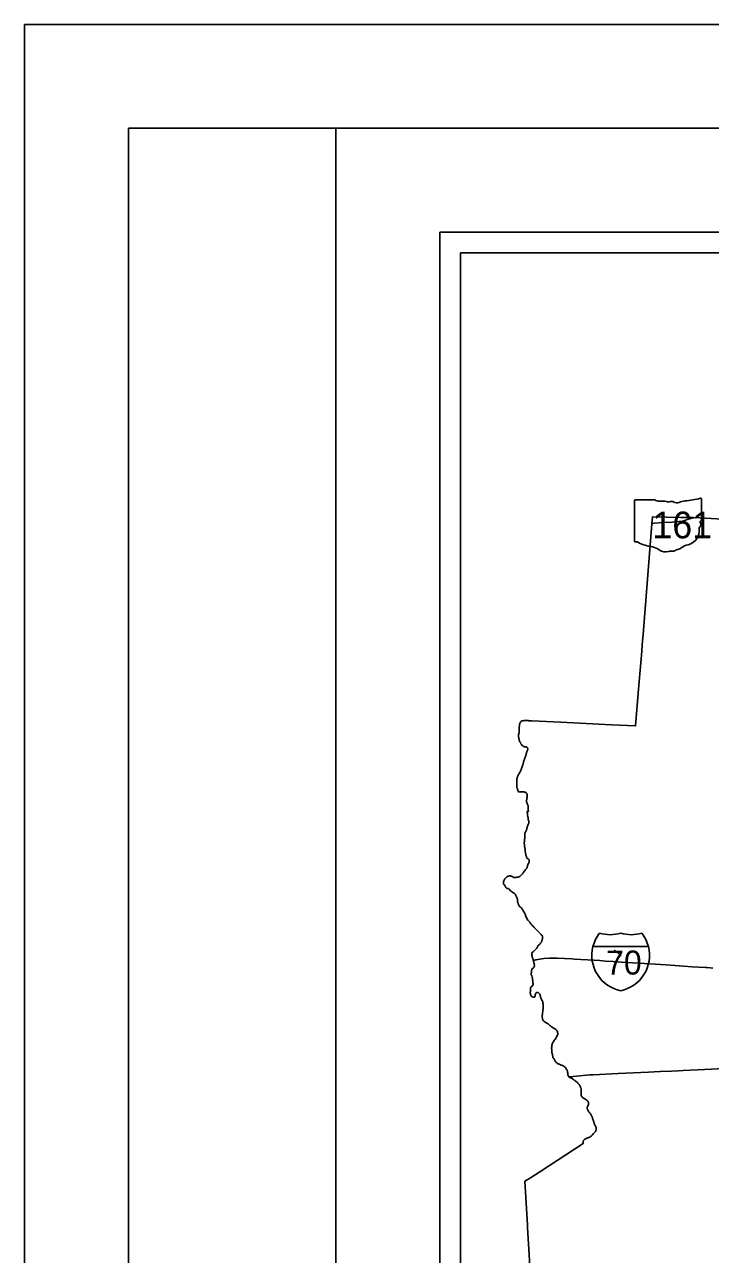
# Model space of a CAD drawing. Extents: x 0 to 34, y 0 to 22.
# Drawn here: x 0 to 3.3, y 16.07 to 22 of the extents above; entities that cross this region are included whole.
import ezdxf

# ---------------------------------------------------------------- set-up
doc = ezdxf.new("R2010")
doc.units = 0
for name, color, linetype in [('GM_X_County', 7, 'Continuous'), ('GM_X_County_Road', 7, 'Continuous'), ('GM_X_Interstate_Route', 7, 'Continuous'), ('GM_X_Interstate_Shield', 7, 'Continuous'), ('GM_X_State_Route', 7, 'Continuous'), ('GM_X_State_Shield', 7, 'Continuous'), ('GM_X_US_Route', 7, 'Continuous'), ('SH_Border', 7, 'Continuous'), ('SH_Cut_Line', 7, 'Continuous'), ('SH_Data', 7, 'Continuous')]:
    doc.layers.add(name, color=color, linetype=linetype)

msp = doc.modelspace()

# ---------------------------------------------------------------- linework, layer by layer
at = {"layer": 'GM_X_County'}
msp.add_lwpolyline([(2.4341, 16.0159), (2.4234, 16.2017), (2.4226, 16.2148), (2.4105, 16.4243), (2.4377, 16.4414), (2.4817, 16.4701), (2.6905, 16.6061), (2.6912, 16.6093), (2.6907, 16.6121), (2.6906, 16.6145), (2.691, 16.6169), (2.6917, 16.6199), (2.6941, 16.6229), (2.6973, 16.6251), (2.7005, 16.6273), (2.7036, 16.6292), (2.7061, 16.6306), (2.7092, 16.6321), (2.7116, 16.6334), (2.7142, 16.6343), (2.7174, 16.6353), (2.7197, 16.6361), (2.7232, 16.6376), (2.7265, 16.6396), (2.7297, 16.6424), (2.7328, 16.6455), (2.7361, 16.6487), (2.739, 16.6522), (2.7416, 16.6551), (2.7446, 16.6579), (2.7476, 16.6612), (2.7503, 16.6646), (2.7522, 16.6675), (2.7531, 16.6699), (2.7538, 16.6725), (2.7541, 16.6756), (2.7543, 16.678), (2.754, 16.6804), (2.7532, 16.683), (2.7516, 16.6861), (2.7504, 16.6899), (2.7489, 16.6932), (2.7481, 16.6955), (2.7466, 16.6986), (2.7452, 16.7016), (2.7439, 16.7042), (2.7429, 16.7076), (2.7423, 16.7104), (2.7413, 16.7136), (2.7403, 16.7161), (2.7393, 16.719), (2.7381, 16.7219), (2.7373, 16.7242), (2.7364, 16.7274), (2.7362, 16.7297), (2.7354, 16.7328), (2.7341, 16.7352), (2.7325, 16.7384), (2.7305, 16.7421), (2.7292, 16.7446), (2.7278, 16.7474), (2.7254, 16.7508), (2.7236, 16.7534), (2.7218, 16.7557), (2.7189, 16.7595), (2.7172, 16.762), (2.7156, 16.7644), (2.7141, 16.7667), (2.7126, 16.77), (2.7114, 16.7732), (2.7108, 16.7757), (2.7105, 16.7781), (2.7107, 16.781), (2.7119, 16.7845), (2.7136, 16.7869), (2.7158, 16.7906), (2.7167, 16.793), (2.7171, 16.7953), (2.7173, 16.7989), (2.717, 16.8017), (2.7164, 16.8044), (2.7158, 16.8068), (2.7145, 16.8098), (2.7117, 16.8128), (2.7088, 16.8149), (2.7039, 16.8183), (2.7016, 16.8195), (2.6987, 16.8211), (2.6956, 16.823), (2.6924, 16.8251), (2.6899, 16.8271), (2.6876, 16.829), (2.6848, 16.8318), (2.6826, 16.8349), (2.6819, 16.8377), (2.6816, 16.8406), (2.6816, 16.8437), (2.6817, 16.8467), (2.6819, 16.8505), (2.682, 16.8539), (2.6821, 16.8571), (2.682, 16.8603), (2.6817, 16.8627), (2.6814, 16.8662), (2.6811, 16.8691), (2.68, 16.874), (2.6791, 16.8769), (2.6782, 16.8794), (2.6766, 16.8826), (2.6755, 16.885), (2.6737, 16.888), (2.6713, 16.8907), (2.6689, 16.8935), (2.6657, 16.8966), (2.6634, 16.8998), (2.6609, 16.9026), (2.6579, 16.9053), (2.6549, 16.9075), (2.6518, 16.9095), (2.6485, 16.912), (2.6427, 16.9162), (2.6403, 16.9175), (2.6375, 16.9193), (2.6343, 16.9209), (2.6318, 16.9222), (2.6287, 16.9234), (2.6263, 16.9244), (2.6231, 16.9268), (2.622, 16.9284), (2.6205, 16.9308), (2.6189, 16.934), (2.6179, 16.9372), (2.6171, 16.9408), (2.6169, 16.9432), (2.6168, 16.9462), (2.6166, 16.9499), (2.6161, 16.9524), (2.6151, 16.9557), (2.6142, 16.9584), (2.613, 16.9607), (2.6113, 16.9637), (2.6096, 16.9668), (2.6084, 16.9691), (2.606, 16.9722), (2.6036, 16.9741), (2.6012, 16.9761), (2.5979, 16.9786), (2.5947, 16.9803), (2.5923, 16.9816), (2.59, 16.9827), (2.5877, 16.9835), (2.5853, 16.9847), (2.5822, 16.9857), (2.5799, 16.9866), (2.5775, 16.9878), (2.575, 16.9887), (2.5725, 16.9897), (2.5702, 16.9908), (2.5672, 16.992), (2.564, 16.9945), (2.5613, 16.9972), (2.5591, 17.0003), (2.5564, 17.0036), (2.5541, 17.0068), (2.5524, 17.0103), (2.551, 17.0127), (2.5497, 17.0154), (2.5474, 17.019), (2.5459, 17.0221), (2.5447, 17.0266), (2.544, 17.0298), (2.5435, 17.0331), (2.5429, 17.0365), (2.5419, 17.0397), (2.541, 17.0429), (2.5404, 17.0457), (2.5402, 17.0481), (2.54, 17.0531), (2.5399, 17.0557), (2.5399, 17.0582), (2.5396, 17.0613), (2.5394, 17.0641), (2.5395, 17.0673), (2.5396, 17.0704), (2.5398, 17.0738), (2.54, 17.0772), (2.5405, 17.0798), (2.5415, 17.0832), (2.5425, 17.0864), (2.5441, 17.0896), (2.5459, 17.0929), (2.5475, 17.0954), (2.5488, 17.0978), (2.5504, 17.1004), (2.5523, 17.1038), (2.5551, 17.1074), (2.5575, 17.1101), (2.5591, 17.1139), (2.5609, 17.117), (2.5627, 17.1202), (2.5645, 17.1227), (2.5663, 17.1262), (2.5676, 17.129), (2.5686, 17.1322), (2.5688, 17.1351), (2.5687, 17.138), (2.5681, 17.1413), (2.5669, 17.1445), (2.566, 17.1475), (2.565, 17.1501), (2.5631, 17.1529), (2.5612, 17.1551), (2.558, 17.1574), (2.5553, 17.1588), (2.5521, 17.1608), (2.5498, 17.1622), (2.5465, 17.1644), (2.5442, 17.166), (2.5415, 17.1677), (2.539, 17.1694), (2.5367, 17.1705), (2.5333, 17.1734), (2.5309, 17.1758), (2.5277, 17.1787), (2.5253, 17.1804), (2.5223, 17.1827), (2.519, 17.1846), (2.5157, 17.1865), (2.5126, 17.1884), (2.5087, 17.1906), (2.5059, 17.1925), (2.5035, 17.194), (2.5002, 17.197), (2.4978, 17.2001), (2.4967, 17.2025), (2.4961, 17.2053), (2.4955, 17.2081), (2.4949, 17.2114), (2.4943, 17.2145), (2.4939, 17.2171), (2.4938, 17.2196), (2.4939, 17.2222), (2.4943, 17.2256), (2.4948, 17.2283), (2.4954, 17.2319), (2.4957, 17.2348), (2.4959, 17.2373), (2.4961, 17.2389), (2.4962, 17.2396), (2.4965, 17.2423), (2.4969, 17.2447), (2.4973, 17.2478), (2.4977, 17.2505), (2.4979, 17.2533), (2.4983, 17.256), (2.4987, 17.2593), (2.4988, 17.2619), (2.499, 17.2643), (2.4991, 17.2667), (2.4993, 17.2691), (2.4992, 17.2718), (2.4989, 17.2748), (2.4986, 17.2775), (2.4977, 17.2836), (2.4971, 17.2867), (2.4965, 17.2895), (2.4949, 17.2927), (2.4935, 17.2952), (2.4923, 17.2977), (2.4912, 17.3), (2.49, 17.3031), (2.4889, 17.306), (2.4875, 17.3092), (2.4864, 17.3119), (2.4856, 17.3151), (2.4851, 17.3174), (2.4843, 17.3204), (2.4837, 17.3227), (2.4821, 17.3261), (2.4808, 17.3284), (2.4778, 17.3317), (2.4749, 17.3338), (2.47, 17.3342), (2.4676, 17.3335), (2.4653, 17.3322), (2.4624, 17.3289), (2.4612, 17.3261), (2.4607, 17.3226), (2.4607, 17.3202), (2.4606, 17.3178), (2.4589, 17.3142), (2.4564, 17.3123), (2.4541, 17.3117), (2.4513, 17.3113), (2.445, 17.3135), (2.4421, 17.3156), (2.4398, 17.3186), (2.4384, 17.3216), (2.4373, 17.3244), (2.437, 17.3271), (2.4365, 17.3303), (2.4365, 17.3328), (2.4367, 17.336), (2.4369, 17.3391), (2.4371, 17.3415), (2.4374, 17.3446), (2.4377, 17.3479), (2.438, 17.3502), (2.4381, 17.353), (2.4377, 17.3562), (2.4396, 17.3595), (2.4428, 17.3624), (2.4459, 17.3644), (2.4493, 17.3699), (2.4498, 17.3724), (2.4498, 17.3749), (2.4497, 17.378), (2.4495, 17.3806), (2.4488, 17.3841), (2.4484, 17.3872), (2.4481, 17.3898), (2.4478, 17.3944), (2.4477, 17.3967), (2.4474, 17.3992), (2.4469, 17.4023), (2.4464, 17.4046), (2.4454, 17.4078), (2.4436, 17.4149), (2.4422, 17.418), (2.4414, 17.421), (2.4412, 17.4241), (2.4413, 17.4271), (2.4416, 17.4303), (2.4419, 17.4333), (2.4422, 17.4357), (2.4425, 17.4386), (2.4428, 17.4417), (2.4437, 17.4447), (2.4464, 17.4492), (2.45, 17.4508), (2.4522, 17.4538), (2.4544, 17.4566), (2.4557, 17.4596), (2.4562, 17.4628), (2.4562, 17.4661), (2.4557, 17.4693), (2.4554, 17.472), (2.4549, 17.4746), (2.4539, 17.4778), (2.4537, 17.4788), (2.453, 17.4812), (2.4525, 17.4839), (2.4517, 17.4865), (2.4511, 17.4883), (2.4498, 17.493), (2.4487, 17.4958), (2.448, 17.4988), (2.447, 17.5019), (2.446, 17.5047), (2.445, 17.5112), (2.4439, 17.5142), (2.4435, 17.5175), (2.4437, 17.5208), (2.4445, 17.5233), (2.4476, 17.528), (2.4504, 17.531), (2.4531, 17.5337), (2.4556, 17.5359), (2.4589, 17.539), (2.4617, 17.5419), (2.4654, 17.5452), (2.4674, 17.548), (2.4697, 17.5515), (2.4714, 17.5546), (2.4726, 17.5577), (2.4748, 17.5612), (2.4781, 17.5645), (2.4805, 17.5664), (2.4834, 17.5693), (2.4857, 17.5717), (2.4885, 17.5748), (2.4898, 17.5772), (2.491, 17.5796), (2.4923, 17.5827), (2.4932, 17.5857), (2.4943, 17.5893), (2.4949, 17.5924), (2.4955, 17.5957), (2.4958, 17.5997), (2.4956, 17.6021), (2.4948, 17.6052), (2.4932, 17.6083), (2.4903, 17.6112), (2.4884, 17.6137), (2.4852, 17.617), (2.4823, 17.6203), (2.4794, 17.6231), (2.4763, 17.6267), (2.4736, 17.6295), (2.4703, 17.6329), (2.4679, 17.6355), (2.4652, 17.638), (2.462, 17.6414), (2.4589, 17.6448), (2.4559, 17.6475), (2.4529, 17.6506), (2.45, 17.6541), (2.4459, 17.6578), (2.4429, 17.6606), (2.4402, 17.6639), (2.4378, 17.667), (2.436, 17.6698), (2.4339, 17.6728), (2.4314, 17.676), (2.429, 17.6787), (2.4254, 17.6834), (2.4204, 17.6906), (2.4177, 17.6962), (2.4142, 17.7033), (2.4132, 17.7065), (2.4129, 17.7093), (2.4123, 17.7116), (2.411, 17.7147), (2.409, 17.7178), (2.4058, 17.7227), (2.4025, 17.7285), (2.3988, 17.7338), (2.3974, 17.7361), (2.3957, 17.7386), (2.3934, 17.7417), (2.3907, 17.7447), (2.3881, 17.7472), (2.3851, 17.749), (2.3825, 17.752), (2.3811, 17.7548), (2.3799, 17.7581), (2.3788, 17.7606), (2.3776, 17.7642), (2.3765, 17.7673), (2.3757, 17.7701), (2.3752, 17.7732), (2.375, 17.7766), (2.3749, 17.779), (2.3747, 17.7819), (2.3743, 17.7846), (2.3737, 17.7877), (2.373, 17.7901), (2.3719, 17.7925), (2.3707, 17.7949), (2.3689, 17.798), (2.3671, 17.8015), (2.3655, 17.8044), (2.3633, 17.8077), (2.3614, 17.81), (2.3587, 17.8128), (2.3557, 17.8145), (2.3525, 17.8167), (2.3502, 17.8177), (2.347, 17.8197), (2.3443, 17.822), (2.3412, 17.8251), (2.3381, 17.8285), (2.3354, 17.8316), (2.333, 17.8338), (2.3306, 17.835), (2.3279, 17.8357), (2.3253, 17.836), (2.3228, 17.8364), (2.3202, 17.8388), (2.3186, 17.8411), (2.3172, 17.8437), (2.315, 17.8473), (2.3133, 17.8501), (2.3115, 17.8525), (2.3095, 17.8555), (2.3082, 17.8587), (2.3075, 17.8621), (2.3075, 17.8646), (2.3076, 17.867), (2.3081, 17.8702), (2.309, 17.8726), (2.3102, 17.8758), (2.3115, 17.8782), (2.3138, 17.8816), (2.3158, 17.8842), (2.3183, 17.8871), (2.3216, 17.8896), (2.324, 17.8915), (2.3266, 17.8932), (2.33, 17.8946), (2.3325, 17.8954), (2.335, 17.8962), (2.3375, 17.8964), (2.3398, 17.8964), (2.3428, 17.8957), (2.3461, 17.8945), (2.3492, 17.893), (2.3533, 17.8907), (2.3565, 17.8893), (2.3601, 17.8884), (2.363, 17.8881), (2.3656, 17.8884), (2.3694, 17.8891), (2.3724, 17.8897), (2.3751, 17.8902), (2.3776, 17.8908), (2.3808, 17.8919), (2.3834, 17.8928), (2.3866, 17.8939), (2.3895, 17.8959), (2.3931, 17.9004), (2.3957, 17.9037), (2.3983, 17.9069), (2.4006, 17.9092), (2.4032, 17.9127), (2.4058, 17.9159), (2.4076, 17.9185), (2.4099, 17.9215), (2.4121, 17.9245), (2.4136, 17.9269), (2.4167, 17.9301), (2.4193, 17.9341), (2.4208, 17.9371), (2.4219, 17.9403), (2.4224, 17.9429), (2.4233, 17.9461), (2.4244, 17.9497), (2.4261, 17.9538), (2.4273, 17.9562), (2.4296, 17.9597), (2.4305, 17.9621), (2.4311, 17.9648), (2.4313, 17.9674), (2.4312, 17.9707), (2.4305, 17.9744), (2.4286, 17.9775), (2.4256, 17.9793), (2.4218, 17.981), (2.4203, 17.9829), (2.4197, 17.9836), (2.4188, 17.9868), (2.4177, 17.99), (2.4164, 17.9934), (2.4158, 17.9958), (2.4152, 17.9981), (2.4144, 18.0014), (2.4138, 18.0047), (2.4132, 18.0077), (2.4128, 18.01), (2.4124, 18.0124), (2.4121, 18.0147), (2.4118, 18.0179), (2.4117, 18.0204), (2.4114, 18.0241), (2.4112, 18.0274), (2.4107, 18.0305), (2.4099, 18.0328), (2.4092, 18.0361), (2.4086, 18.0393), (2.4082, 18.043), (2.408, 18.0453), (2.4079, 18.0487), (2.4077, 18.0514), (2.4076, 18.0544), (2.4075, 18.057), (2.4076, 18.0595), (2.408, 18.0624), (2.4082, 18.0648), (2.4084, 18.0677), (2.4088, 18.0707), (2.4093, 18.0742), (2.4097, 18.0768), (2.41, 18.0793), (2.4103, 18.0828), (2.4103, 18.0861), (2.4103, 18.0891), (2.4105, 18.0919), (2.4105, 18.0942), (2.4107, 18.0965), (2.4108, 18.0991), (2.4109, 18.1016), (2.4119, 18.1052), (2.4139, 18.1081), (2.4157, 18.1112), (2.4169, 18.1142), (2.4182, 18.1174), (2.4188, 18.12), (2.4196, 18.1223), (2.4204, 18.1255), (2.4214, 18.1294), (2.4221, 18.132), (2.4233, 18.1361), (2.4239, 18.1384), (2.4253, 18.1423), (2.4266, 18.1448), (2.428, 18.1477), (2.4295, 18.1512), (2.4299, 18.1536), (2.4298, 18.156), (2.4296, 18.1583), (2.4291, 18.1606), (2.4283, 18.163), (2.4277, 18.1653), (2.427, 18.1682), (2.4266, 18.171), (2.4262, 18.1734), (2.4261, 18.1758), (2.4257, 18.1782), (2.4252, 18.1806), (2.4242, 18.1834), (2.4233, 18.186), (2.423, 18.1885), (2.4234, 18.1909), (2.4239, 18.1939), (2.4237, 18.1963), (2.4225, 18.1994), (2.4212, 18.2018), (2.4204, 18.2053), (2.4223, 18.2079), (2.4247, 18.2076), (2.4273, 18.2069), (2.4272, 18.2094), (2.427, 18.2123), (2.4269, 18.2153), (2.4266, 18.2186), (2.4266, 18.2235), (2.4265, 18.2261), (2.4264, 18.2299), (2.426, 18.2334), (2.425, 18.2368), (2.4236, 18.2399), (2.4226, 18.2423), (2.4216, 18.2449), (2.42, 18.2481), (2.4193, 18.2506), (2.4186, 18.2533), (2.4182, 18.2565), (2.4184, 18.2595), (2.4189, 18.2622), (2.4193, 18.2649), (2.4197, 18.2675), (2.4205, 18.2718), (2.4211, 18.2754), (2.4213, 18.2776), (2.4217, 18.2801), (2.4218, 18.2827), (2.4215, 18.2853), (2.4211, 18.2884), (2.4201, 18.2916), (2.4177, 18.2955), (2.4153, 18.2976), (2.412, 18.2997), (2.4086, 18.3007), (2.4055, 18.3012), (2.4018, 18.3014), (2.3995, 18.3012), (2.3964, 18.3012), (2.3929, 18.3014), (2.3893, 18.3008), (2.3858, 18.3007), (2.3826, 18.3011), (2.3795, 18.3021), (2.3774, 18.305), (2.3768, 18.3082), (2.3758, 18.3112), (2.3751, 18.3139), (2.374, 18.3172), (2.373, 18.3202), (2.3723, 18.323), (2.3719, 18.3256), (2.3714, 18.3286), (2.371, 18.3318), (2.3709, 18.3343), (2.3709, 18.3379), (2.3712, 18.3407), (2.3715, 18.3434), (2.3719, 18.346), (2.3722, 18.3489), (2.3722, 18.3543), (2.3722, 18.3575), (2.3721, 18.3599), (2.3721, 18.3623), (2.3723, 18.3649), (2.3726, 18.3676), (2.3732, 18.3704), (2.3743, 18.3733), (2.3757, 18.3764), (2.3771, 18.3798), (2.3785, 18.3823), (2.3802, 18.3856), (2.3822, 18.3891), (2.3839, 18.3924), (2.386, 18.3957), (2.3876, 18.3985), (2.3891, 18.4016), (2.3905, 18.4046), (2.3918, 18.407), (2.3931, 18.4104), (2.3942, 18.4137), (2.3952, 18.4161), (2.3963, 18.4189), (2.3977, 18.4231), (2.3984, 18.4255), (2.3992, 18.4286), (2.4003, 18.4316), (2.4018, 18.4347), (2.4023, 18.4376), (2.4026, 18.4404), (2.4031, 18.443), (2.4037, 18.4462), (2.4049, 18.4496), (2.4055, 18.4521), (2.4068, 18.4554), (2.4085, 18.4589), (2.4101, 18.4626), (2.4109, 18.4654), (2.4122, 18.4692), (2.4133, 18.4725), (2.4143, 18.4755), (2.4153, 18.479), (2.4159, 18.4816), (2.4167, 18.4849), (2.4175, 18.488), (2.4184, 18.4907), (2.4199, 18.4938), (2.4218, 18.4973), (2.4231, 18.5024), (2.4247, 18.5088), (2.4243, 18.5115), (2.4225, 18.5144), (2.4193, 18.5169), (2.4166, 18.5179), (2.4134, 18.5186), (2.4116, 18.5191), (2.4078, 18.5192), (2.4047, 18.5196), (2.4016, 18.5214), (2.3985, 18.5243), (2.3958, 18.5272), (2.3937, 18.5303), (2.3913, 18.5335), (2.3888, 18.5386), (2.3869, 18.5419), (2.3853, 18.5452), (2.3843, 18.5475), (2.3836, 18.5503), (2.383, 18.5529), (2.3823, 18.5557), (2.3816, 18.5588), (2.3809, 18.5613), (2.3804, 18.5649), (2.3802, 18.5675), (2.3802, 18.5698), (2.3801, 18.5729), (2.3803, 18.5759), (2.3805, 18.5782), (2.3817, 18.5834), (2.3822, 18.586), (2.3828, 18.5896), (2.3831, 18.5929), (2.3834, 18.5958), (2.3836, 18.5983), (2.3836, 18.6048), (2.3836, 18.6084), (2.3835, 18.6108), (2.3835, 18.6138), (2.3837, 18.6162), (2.3839, 18.6185), (2.3841, 18.6219), (2.3845, 18.6248), (2.3852, 18.6274), (2.3859, 18.6307), (2.3872, 18.6339), (2.3897, 18.6373), (2.3918, 18.6405), (2.3949, 18.6434), (2.3972, 18.6443), (2.4003, 18.6446), (2.4036, 18.6446), (2.4057, 18.6447), (2.4063, 18.6447), (2.4092, 18.6448), (2.4124, 18.6449), (2.4149, 18.645), (2.4183, 18.645), (2.4209, 18.645), (2.4238, 18.6452), (2.4263, 18.645), (2.4296, 18.6442), (2.4326, 18.6441), (2.4358, 18.6439), (2.4384, 18.6441), (2.4421, 18.6442), (2.4446, 18.6442), (2.5841, 18.6373), (2.8271, 18.6252), (2.9441, 18.6194), (2.96, 18.8159), (2.9673, 18.9064), (2.9733, 18.9802), (2.9758, 19.0108), (2.9813, 19.0797), (2.9814, 19.0807), (3.0228, 19.5928), (3.0256, 19.6275), (3.1605, 19.6246), (3.2226, 19.6232), (3.3645, 19.616)], dxfattribs=at)
at = {"layer": 'GM_X_County_Road'}
msp.add_lwpolyline([(2.8746, 17.5089), (2.8712, 17.5127), (2.8654, 17.5185), (2.858, 17.5247), (2.8472, 17.5333), (2.8414, 17.5376)], dxfattribs=at)
at = {"layer": 'GM_X_Interstate_Route'}
for points in [[(2.4524, 17.4883), (2.4632, 17.4915), (2.5024, 17.4975), (2.529, 17.4996), (2.5667, 17.5004), (2.6362, 17.4963), (2.6503, 17.4953), (2.7427, 17.4894), (2.7717, 17.4881), (2.7996, 17.4858), (2.8364, 17.4837), (2.876, 17.4806), (2.9572, 17.4749), (3.091, 17.4676), (3.2164, 17.4586), (3.281, 17.4545), (3.2834, 17.4544), (3.287, 17.4541)], [(3.287, 17.4541), (3.2894, 17.454)], [(3.2894, 17.454), (3.3034, 17.4531), (3.3164, 17.4523)]]:
    msp.add_lwpolyline(points, dxfattribs=at)
at = {"layer": 'GM_X_Interstate_Shield'}
for p, q in [((2.7385, 17.5553), (3.0056, 17.5553)), ((3.0056, 17.5553), (2.7385, 17.5553)), ((3.0056, 17.5553), (2.7385, 17.5553))]:
    msp.add_line(p, q, dxfattribs=at)
for centre, start, end in [((2.9068, 17.5128), 141.66896, 165.80665), ((2.8214, 17.7863), 253.00908, 286.99093), ((2.9228, 17.7863), 253.00908, 286.99093), ((2.8374, 17.5128), 14.19335, 38.33104), ((2.9068, 17.5128), 165.80665, 258.46304), ((2.8374, 17.5128), 281.53696, 14.19335)]:
    msp.add_arc(centre, 0.1735, start, end, dxfattribs=at)
at = {"layer": 'GM_X_State_Route'}
msp.add_lwpolyline([(3.0222, 19.5955), (3.0334, 19.596), (3.0839, 19.5994), (3.1207, 19.6015), (3.1447, 19.603), (3.1533, 19.6041), (3.1627, 19.6054), (3.1762, 19.6087), (3.1976, 19.6154), (3.2218, 19.6229), (3.2226, 19.6232)], dxfattribs=at)
at = {"layer": 'GM_X_State_Shield'}
for p, q in [((2.9387, 19.7054), (2.9387, 19.5099)), ((3.0362, 19.7088), (2.9419, 19.7088)), ((3.2608, 19.6113), (3.2608, 19.7137)), ((3.2608, 19.6114), (3.2608, 19.6113))]:
    msp.add_line(p, q, dxfattribs=at)
for centre, major_axis, start_param, end_param in [((2.9424, 19.7059), (0.00373, 0), 1.712693, 3.28349), ((3.0587, 19.7315), (0.0362, 0), 4.042523, 4.731795), ((3.0707, 19.599), (0.1299, 0), 1.404758, 1.657858), ((3.1002, 19.7069), (0.0104, 0), 3.836095, 5.185415), ((3.1155, 19.6843), (0.0217, 0), 0.950623, 2.079405), ((3.1436, 19.7153), (0.0261, 0), 4.081561, 5.145723), ((3.1897, 19.6491), (0.0687, 0), 1.699011, 2.107814), ((3.1461, 19.9755), (0.3416, 0), 4.814394, 5.042369), ((3.2573, 19.7141), (0.00359, 0), 6.141152, 7.989035), ((3.1652, 19.5555), (0.0854, 0), 5.101752, 6.440018), ((3.2737, 19.5685), (0.0242, 0), 2.387724, 3.262537), ((3.26, 19.6038), (0.00555, 0), 1.883978, 3.671073), ((3.2247, 19.5909), (0.0333, 0), 5.934695, 6.695948), ((3.257, 19.6109), (0.00384, 0), 5.05454, 6.418171), ((2.9425, 19.5094), (0.00376, 0), 3.00124, 4.508301), ((2.943, 19.5294), (0.0287, 0), 4.665946, 4.897461), ((2.9489, 19.4986), (0.0104, 0), 0.519207, 1.627899), ((3.0797, 19.6743), (0.2467, 0), 4.195997, 4.488961), ((3.0062, 19.422), (0.0772, 0), 0.823519, 1.323587), ((3.0896, 19.4976), (0.049, 0), 4.026481, 4.996735), ((3.1179, 19.43), (0.0402, 0), 1.495662, 1.94098), ((3.1215, 19.483), (0.0261, 0), 4.691044, 5.507374), ((3.1451, 19.464), (0.00735, 0), 1.147584, 2.315152), ((3.142, 19.4909), (0.0276, 0), 4.937069, 5.64225), ((3.2013, 19.4549), (0.0468, 0), 1.647645, 2.488434)]:
    msp.add_ellipse(centre, major_axis=major_axis, ratio=0.8, start_param=start_param, end_param=end_param, dxfattribs=at)
at = {"layer": 'GM_X_US_Route'}
for points in [[(2.7395, 16.9377), (2.86, 16.9439), (3.0062, 16.9501), (3.0606, 16.9531), (3.0639, 16.9531), (3.1164, 16.9556), (3.1504, 16.9574), (3.1738, 16.9585), (3.2764, 16.9634), (3.3714, 16.9682)], [(2.6268, 16.9285), (2.7227, 16.9369), (2.7395, 16.9377)]]:
    msp.add_lwpolyline(points, dxfattribs=at)
at = {"layer": 'SH_Border'}
for points in [[(0.5, 21.5), (1.5, 21.5), (1.5, 0.5), (0.5, 0.5)], [(1.5, 21.5), (33.5, 21.5), (33.5, 0.5), (1.5, 0.5)]]:
    msp.add_lwpolyline(points, close=True, dxfattribs=at)
at = {"layer": 'SH_Cut_Line'}
msp.add_lwpolyline([(0, 0), (34, 0), (34, 22), (0, 22)], close=True, dxfattribs=at)
at = {"layer": 'SH_Data'}
for p, q in [((2, 21), (9, 21)), ((2, 21), (2, 14)), ((2.1, 20.9), (2.1, 14.1)), ((2.1, 20.9), (8.9, 20.9))]:
    msp.add_line(p, q, dxfattribs=at)

# ---------------------------------------------------------------- texts
at = {"layer": 'GM_X_Interstate_Shield'}
msp.add_text('70', height=0.11569, dxfattribs=at).set_placement((2.8015, 17.4208))
at = {"layer": 'GM_X_State_Shield'}
msp.add_text('161', height=0.12885, dxfattribs=at).set_placement((3.0249, 19.5236))

doc.saveas('drawing.dxf')
